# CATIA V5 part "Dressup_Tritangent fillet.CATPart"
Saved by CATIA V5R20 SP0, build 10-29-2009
Part number: Tritangent fillet
Bounding box of the stored display mesh (mm): x -66.409 to 0, y 0 to 108.689, z 0 to 50
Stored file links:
  G:\카티아자료\수업자료\툴바예제\2 PartDesign\01.PartDesign\2_Dress Up Featrues\1_Fillet\4_Tritangent fillet.CATPart
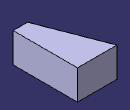
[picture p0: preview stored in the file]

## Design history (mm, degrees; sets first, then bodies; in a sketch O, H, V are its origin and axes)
Body1 (main body)
  Sketch1 on xy-plane, origin (0, 0, 0), H (1, 0, 0), V (0, 1, 0)
    line L1 (0, 0) -> (-24.3384, 0)
    line L2 (-24.3384, 0) -> (-66.409, 108.6889)
    line L3 (-66.409, 108.6889) -> (0, 108.6889)
    point P3 (0, 108.6889)
    line L4 (0, 108.6889) -> (0, 0)
    horizontal: L1 H, L3 H
    coincidence: P3 V
    vertical: L4 V
  Pad1 "Pad.1": profile Sketch1, direction (0, 0, 1), length 50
